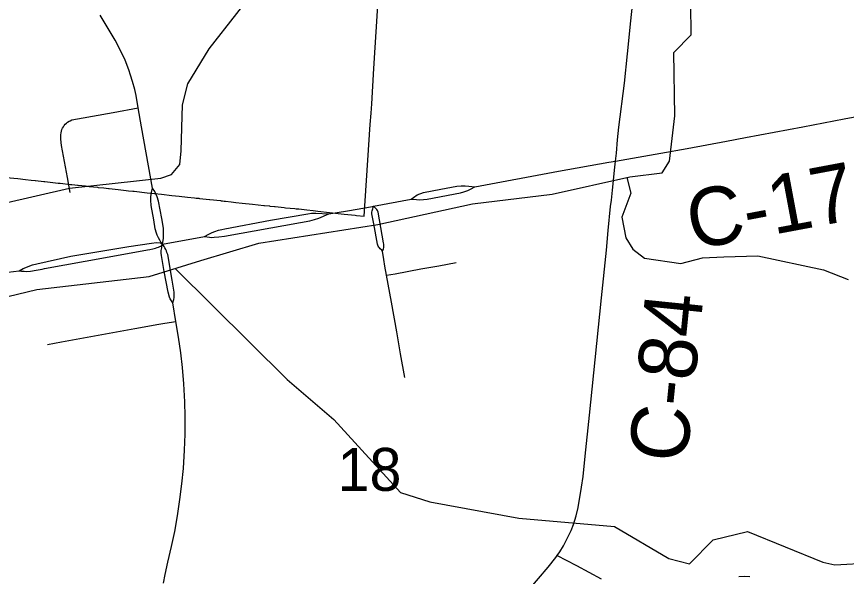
# Model space of a CAD drawing. Extents: x -1.4 to 35.4, y 0 to 22.
# Drawn here: x 29.718 to 30.527, y 14.766 to 15.312 of the extents above; entities that cross this region are included whole.
import ezdxf

# ---------------------------------------------------------------- set-up
doc = ezdxf.new("R2010")
doc.units = 0
for name, color, linetype in [('GM_X_City_Street', 7, 'Continuous'), ('GM_X_County_Road', 7, 'Continuous'), ('GM_X_County_Road_Text', 7, 'Continuous'), ('GM_X_County_Text', 7, 'Continuous'), ('GM_X_Minor_River', 7, 'Continuous'), ('GM_X_Section_Text', 7, 'Continuous')]:
    doc.layers.add(name, color=color, linetype=linetype)

msp = doc.modelspace()

# ---------------------------------------------------------------- linework, layer by layer
at = {"layer": 'GM_X_City_Street'}
for points in [[(29.85031, 15.14483), (29.84646, 15.16659), (29.83959, 15.20453), (29.83651, 15.22289), (29.83428, 15.23511), (29.83295, 15.24084), (29.83076, 15.24888), (29.82902, 15.25482), (29.82723, 15.26014), (29.82366, 15.26942), (29.81926, 15.27902), (29.81396, 15.28886), (29.79929, 15.31339)], [(29.76995, 15.14052), (29.76744, 15.15517), (29.76171, 15.18629), (29.76089, 15.19245), (29.76083, 15.19431), (29.7609, 15.19678), (29.76117, 15.19871), (29.76155, 15.20044), (29.76204, 15.20198), (29.76264, 15.20332), (29.76346, 15.20466), (29.76429, 15.20594), (29.76527, 15.2071), (29.76642, 15.20819), (29.76757, 15.20907), (29.76895, 15.20995), (29.77005, 15.21053), (29.77178, 15.2112), (29.77723, 15.21238), (29.81205, 15.2185), (29.83651, 15.22289)], [(29.87019, 15.03303), (29.86878, 15.03497), (29.8676, 15.0368), (29.86684, 15.03853), (29.86555, 15.04327), (29.86185, 15.0635), (29.85909, 15.07903), (29.85878, 15.08125), (29.85878, 15.08288), (29.8588, 15.08393), (29.85901, 15.08533), (29.85928, 15.08669), (29.8596, 15.08805), (29.8601, 15.09004), (29.85847, 15.09222), (29.85738, 15.09405), (29.85625, 15.09638), (29.85504, 15.09883), (29.85418, 15.10097), (29.85297, 15.10513), (29.85159, 15.1138), (29.84911, 15.12783), (29.84874, 15.1329), (29.84879, 15.13624), (29.84929, 15.14034), (29.85031, 15.14483)], [(29.87019, 15.03303), (29.87115, 15.03626), (29.87137, 15.03799), (29.87148, 15.03993), (29.87148, 15.04144), (29.87135, 15.04341), (29.86953, 15.05503), (29.86516, 15.07996), (29.86446, 15.08195), (29.86387, 15.08358), (29.86321, 15.08502), (29.86251, 15.08654), (29.86181, 15.08771), (29.8601, 15.09004), (29.86076, 15.09385), (29.861, 15.09596), (29.86111, 15.09864), (29.86111, 15.10094), (29.86115, 15.10354), (29.86107, 15.10584), (29.85934, 15.11523), (29.85606, 15.13197), (29.85476, 15.1363), (29.85349, 15.13933), (29.85248, 15.14145), (29.85031, 15.14483)], [(30.07486, 15.08344), (30.07389, 15.0843), (30.07258, 15.08561), (30.07179, 15.0864), (30.07106, 15.08735), (30.07063, 15.08813), (30.07016, 15.08914), (30.06979, 15.09029), (30.06623, 15.10991), (30.06444, 15.11976), (30.06437, 15.12125), (30.06456, 15.12266), (30.06512, 15.12465), (30.0659, 15.12714)], [(30.07486, 15.08344), (30.07552, 15.08556), (30.07587, 15.08674), (30.07605, 15.08813), (30.07605, 15.08923), (30.07599, 15.09029), (30.07583, 15.0915), (30.07044, 15.12133), (30.06974, 15.12286), (30.06918, 15.1238), (30.06852, 15.12465), (30.0659, 15.12714)], [(30.09643, 14.96), (30.09227, 14.9833), (30.0886, 15.00478), (30.08351, 15.03362), (30.07872, 15.05978), (30.07707, 15.06879), (30.07613, 15.07509), (30.07486, 15.08344)], [(30.07872, 15.05978), (30.08696, 15.06129), (30.11219, 15.06593), (30.12959, 15.0691), (30.14661, 15.07236)], [(29.86105, 14.75949), (29.86255, 14.7681), (29.86529, 14.78026), (29.86883, 14.79539), (29.87199, 14.80994), (29.87474, 14.8252), (29.87714, 14.84115), (29.87903, 14.85655), (29.88042, 14.87138), (29.88151, 14.88933), (29.88207, 14.90484), (29.88218, 14.92221), (29.8818, 14.93648), (29.88086, 14.95382), (29.87956, 14.96989), (29.87791, 14.98406), (29.87564, 14.9994), (29.87314, 15.01484), (29.87019, 15.03303)], [(29.74794, 14.99239), (29.76141, 14.99489), (29.83311, 15.00782), (29.85638, 15.01205), (29.86249, 15.01307), (29.87314, 15.01484)], [(30.24509, 14.78654), (30.25391, 14.78199), (30.26387, 14.77684), (30.28786, 14.76371)], [(30.42246, 14.76605), (30.4275, 14.76632), (30.43316, 14.7662)]]:
    msp.add_lwpolyline(points, dxfattribs=at)
at = {"layer": 'GM_X_County_Road'}
for p, q in [((30.0659, 15.12714), (30.10261, 15.134)), ((29.8601, 15.09004), (29.90102, 15.09749))]:
    msp.add_line(p, q, dxfattribs=at)
for points in [[(30.30201, 15.17117), (30.30281, 15.17875), (30.30408, 15.19172), (30.30536, 15.20409), (30.31077, 15.24723), (30.3138, 15.27563), (30.31706, 15.30776), (30.31952, 15.33249), (30.32091, 15.34979), (30.32117, 15.35426)], [(30.30201, 15.17117), (30.34633, 15.17885), (30.37199, 15.18345), (30.41041, 15.19067), (30.42873, 15.194), (30.48488, 15.20465), (30.52517, 15.21227), (30.57095, 15.22082), (30.59398, 15.22532)], [(30.16468, 15.14589), (30.24644, 15.16139), (30.29535, 15.17), (30.30201, 15.17117)], [(30.26562, 14.8334), (30.26887, 14.85321), (30.27037, 14.86362), (30.27253, 14.88336), (30.27655, 14.92354), (30.27912, 14.94888), (30.28819, 15.03788), (30.29313, 15.08421), (30.29498, 15.10337), (30.29727, 15.12687), (30.29794, 15.13304), (30.29896, 15.14293), (30.30138, 15.16517), (30.30201, 15.17117)], [(30.10261, 15.134), (30.10478, 15.13569), (30.10849, 15.1381), (30.11461, 15.14042), (30.13152, 15.14368), (30.14725, 15.14663), (30.1516, 15.14709), (30.15522, 15.14709), (30.15884, 15.14682), (30.16468, 15.14589)], [(30.10261, 15.134), (30.10775, 15.13356), (30.11118, 15.13346), (30.11471, 15.13365), (30.11839, 15.13406), (30.15068, 15.14031), (30.15411, 15.14116), (30.1581, 15.14246), (30.16134, 15.14394), (30.16468, 15.14589)], [(30.02245, 15.11956), (30.04052, 15.12257), (30.06488, 15.12695), (30.0659, 15.12714)], [(29.90102, 15.09749), (29.90535, 15.09981), (29.90869, 15.10138), (29.91129, 15.10249), (29.91481, 15.10379), (29.91787, 15.10454), (29.92075, 15.10519), (29.96542, 15.11338), (30.00178, 15.11984), (30.00558, 15.1202), (30.00956, 15.1203), (30.02245, 15.11956)], [(29.90102, 15.09749), (29.906, 15.09684), (29.90832, 15.09675), (29.91054, 15.09684), (29.915, 15.09721), (29.92056, 15.09795), (29.99486, 15.11129), (30.00383, 15.11291), (30.00845, 15.11409), (30.01244, 15.11548), (30.02245, 15.11956)], [(29.72018, 15.06427), (29.72419, 15.06652), (29.73327, 15.07005), (29.73745, 15.07107), (29.77051, 15.07834), (29.82739, 15.08794), (29.84951, 15.09108), (29.85429, 15.09168), (29.85776, 15.09129), (29.8601, 15.09004)], [(29.74511, 15.06627), (29.80443, 15.07722), (29.84546, 15.08463), (29.8477, 15.08506), (29.8505, 15.08569), (29.85325, 15.08636), (29.85492, 15.08685), (29.85633, 15.08732), (29.8575, 15.08786), (29.85843, 15.08833), (29.85937, 15.089), (29.8601, 15.09004)], [(29.72018, 15.06427), (29.7227, 15.06393), (29.72511, 15.06365), (29.72725, 15.06355), (29.73142, 15.06393), (29.7368, 15.06467), (29.7426, 15.06581), (29.74511, 15.06627)], [(29.68831, 15.06179), (29.69858, 15.06205), (29.70929, 15.0629), (29.72018, 15.06427)], [(30.24509, 14.78654), (30.24764, 14.79014), (30.2512, 14.79595), (30.255, 14.80306), (30.25865, 14.81093), (30.26095, 14.81669), (30.26242, 14.82108), (30.26361, 14.82522), (30.26562, 14.8334)], [(30.17456, 14.70076), (30.191, 14.72113), (30.20448, 14.73735), (30.21761, 14.75304), (30.23635, 14.77536), (30.2437, 14.78457), (30.24509, 14.78654)]]:
    msp.add_lwpolyline(points, dxfattribs=at)
at = {"layer": 'GM_X_County_Text'}
msp.add_lwpolyline([(29.70769, 15.15523), (29.71893, 15.15401), (29.72651, 15.1532), (29.73211, 15.15258), (29.73587, 15.15217), (29.73622, 15.15213), (29.74439, 15.15125), (29.74529, 15.15115), (29.75847, 15.14971), (29.76039, 15.14951), (29.77024, 15.14844), (29.7711, 15.14834), (29.77165, 15.14828), (29.77451, 15.14797), (29.77727, 15.14767), (29.77798, 15.1476), (29.78483, 15.14685), (29.78863, 15.14644), (29.79676, 15.14556), (29.79736, 15.14549), (29.80275, 15.14491), (29.80743, 15.1444), (29.80797, 15.14434), (29.81687, 15.14337), (29.82464, 15.14253), (29.82705, 15.14227), (29.83099, 15.14184), (29.83237, 15.14169), (29.84511, 15.14031), (29.85242, 15.13951), (29.85924, 15.13877), (29.86921, 15.13769), (29.87631, 15.13693), (29.8846, 15.13602), (29.89129, 15.13529), (29.89288, 15.13512), (29.89544, 15.13484), (29.89608, 15.13477), (29.90598, 15.1337), (29.90618, 15.13368), (29.91668, 15.13254), (29.91735, 15.13246), (29.91867, 15.13232), (29.92034, 15.13214), (29.9205, 15.13212), (29.92168, 15.13199), (29.92722, 15.13139), (29.93166, 15.13091), (29.93777, 15.13025), (29.94801, 15.12913), (29.95886, 15.12796), (29.95906, 15.12793), (29.95964, 15.12787), (29.96457, 15.12734), (29.96474, 15.12732), (29.9694, 15.12681), (29.96987, 15.12676), (29.97886, 15.12578), (29.97995, 15.12568), (29.98913, 15.12479), (29.9905, 15.12466), (29.993, 15.12442), (30.00105, 15.12352), (30.00704, 15.12286), (30.01159, 15.12235), (30.02307, 15.12107), (30.03738, 15.11948), (30.0482, 15.11828), (30.04932, 15.11815), (30.05677, 15.11732), (30.06267, 15.20679), (30.06351, 15.21794), (30.06418, 15.22684), (30.06612, 15.26153), (30.07225, 15.35378)], dxfattribs=at)
at = {"layer": 'GM_X_Minor_River'}
for points in [[(29.67157, 15.12218), (29.76929, 15.14471), (29.85843, 15.15462), (29.86872, 15.1582), (29.87685, 15.16789), (29.87825, 15.18113), (29.8795, 15.22584), (29.88483, 15.24659), (29.90556, 15.28066), (29.95951, 15.34969), (30.03018, 15.46008), (30.09291, 15.53234), (30.10332, 15.54198), (30.10924, 15.55437), (30.11825, 15.58945), (30.12782, 15.7106), (30.12844, 15.7231), (30.1316, 15.80646), (30.12831, 15.85128), (30.12874, 15.85442)], [(29.6819, 15.03245), (29.73746, 15.04604), (29.84708, 15.05856), (29.89735, 15.0742), (29.95407, 15.09122), (30.07023, 15.10929), (30.16259, 15.12937), (30.24036, 15.13876), (30.31601, 15.15577), (30.3475, 15.15967), (30.35453, 15.1709), (30.35994, 15.21515), (30.35888, 15.27697), (30.37587, 15.29406), (30.37532, 15.32402)], [(30.31293, 15.15508), (30.31683, 15.13983), (30.30805, 15.11651), (30.31219, 15.09633), (30.31879, 15.08519), (30.33035, 15.07661), (30.36583, 15.07133), (30.38675, 15.07696), (30.40758, 15.07767), (30.44091, 15.07888), (30.50498, 15.06504), (30.52902, 15.05582)], [(29.87233, 15.06641), (29.98174, 14.95834), (30.02714, 14.91911), (30.09236, 14.848), (30.12095, 14.83906), (30.20768, 14.82286), (30.301, 14.81487), (30.35413, 14.78382), (30.37409, 14.77848), (30.39725, 14.80188), (30.43072, 14.80991), (30.50431, 14.77995), (30.51599, 14.77743), (30.55085, 14.77937), (30.57553, 14.78378), (30.60918, 14.78195), (30.6611, 14.76609)]]:
    msp.add_lwpolyline(points, dxfattribs=at)

# ---------------------------------------------------------------- texts
at = {"layer": 'GM_X_County_Road_Text'}
for s, rotation, p in [('C-17', 10.63917, (30.37729, 15.08454)), ('C-84', 84.18778, (30.37127, 14.8759))]:
    msp.add_text(s, height=0.056818, rotation=rotation, dxfattribs=at).set_placement(p)
at = {"layer": 'GM_X_Section_Text'}
msp.add_text('18', height=0.041856, rotation=0.00001, dxfattribs=at).set_placement((30.03089, 14.84964))

doc.saveas('drawing.dxf')
